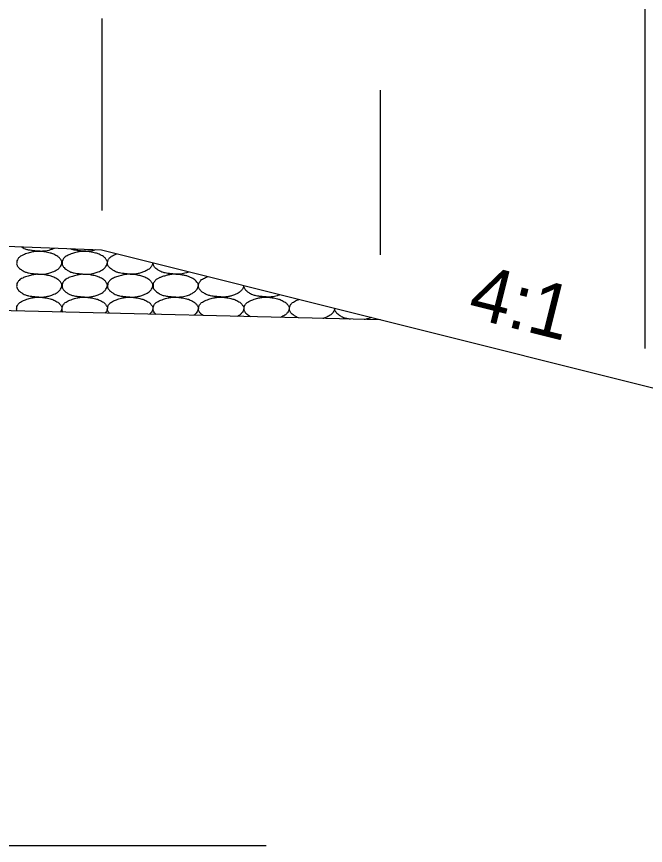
# Model space of a CAD drawing. Extents: x 1671357 to 13005564, y 567358 to 14261451.
# Drawn here: x 12758470.84 to 12758477.78, y 14259921.37 to 14259930.53 of the extents above; entities that cross this region are included whole.
import ezdxf

# ---------------------------------------------------------------- set-up
doc = ezdxf.new("R2010")
doc.units = 0
doc.layers.add('Default', color=7, linetype='Continuous')
doc.layers.add('R_Draft', color=7, linetype='Continuous')

msp = doc.modelspace()

# ---------------------------------------------------------------- linework, layer by layer
at = {"layer": 'Default'}
for p, q in [((12758477.7826, 14259926.8614), (12758477.7826, 14259931.0353)), ((12758471.7821, 14259928.3843), (12758471.7821, 14259930.5053)), ((12758474.8551, 14259927.8956), (12758474.8551, 14259929.7166)), ((12758471.7754, 14259927.947), (12758467.7783, 14259928.1069)), ((12758480.854, 14259925.6767), (12758471.7754, 14259927.947)), ((12758474.8551, 14259927.1769), (12758456.7618, 14259927.6286))]:
    msp.add_line(p, q, dxfattribs=at)
at = {"layer": 'R_Draft'}
msp.add_line((12758441.146, 14259921.3734), (12758473.5951, 14259921.3734), dxfattribs=at)
for points in [[(12758471.2523, 14259927.9679), (12758471.2407, 14259927.9624), (12758471.2289, 14259927.9576), (12758471.188, 14259927.9447), (12758471.1597, 14259927.9375), (12758471.1158, 14259927.9348), (12758471.101, 14259927.9347), (12758471.0644, 14259927.9371), (12758471.0424, 14259927.9393), (12758470.9962, 14259927.9443), (12758470.9723, 14259927.9481), (12758470.9288, 14259927.9582), (12758470.9119, 14259927.9687), (12758470.8929, 14259927.9806), (12758470.8915, 14259927.9815), (12758470.8901, 14259927.9824)], [(12758471.0864, 14259927.9331), (12758471.1157, 14259927.9335), (12758471.1451, 14259927.9291), (12758471.2102, 14259927.9158), (12758471.2432, 14259927.9049), (12758471.2986, 14259927.8752), (12758471.3137, 14259927.8591), (12758471.3347, 14259927.8276), (12758471.3381, 14259927.8167), (12758471.333, 14259927.7883), (12758471.3233, 14259927.7696), (12758471.299, 14259927.7426), (12758471.2898, 14259927.7355), (12758471.2583, 14259927.7176), (12758471.2384, 14259927.708), (12758471.188, 14259927.6921), (12758471.1597, 14259927.6849), (12758471.1158, 14259927.6822), (12758471.101, 14259927.6821), (12758471.0644, 14259927.6845), (12758471.0424, 14259927.6867), (12758470.9962, 14259927.6917), (12758470.9723, 14259927.6955), (12758470.9288, 14259927.7056), (12758470.9119, 14259927.7161), (12758470.8745, 14259927.7395), (12758470.8584, 14259927.7516), (12758470.8372, 14259927.7841), (12758470.8357, 14259927.7959), (12758470.8373, 14259927.8233), (12758470.8407, 14259927.8396), (12758470.8642, 14259927.8707), (12758470.877, 14259927.8791), (12758470.9055, 14259927.8939), (12758470.9185, 14259927.9004), (12758470.9523, 14259927.9118), (12758470.9721, 14259927.9178), (12758471.005, 14259927.9264), (12758471.0176, 14259927.9291), (12758471.0489, 14259927.934), (12758471.0678, 14259927.9347), (12758471.0864, 14259927.9331)], [(12758471.5888, 14259927.9331), (12758471.6181, 14259927.9335), (12758471.6475, 14259927.9291), (12758471.7126, 14259927.9158), (12758471.7456, 14259927.9049), (12758471.801, 14259927.8752), (12758471.8161, 14259927.8591), (12758471.8372, 14259927.8276), (12758471.8406, 14259927.8167), (12758471.8355, 14259927.7883), (12758471.8257, 14259927.7696), (12758471.8015, 14259927.7426), (12758471.7922, 14259927.7355), (12758471.7607, 14259927.7176), (12758471.7408, 14259927.708), (12758471.6904, 14259927.6921), (12758471.6621, 14259927.6849), (12758471.6182, 14259927.6822), (12758471.6034, 14259927.6821), (12758471.5668, 14259927.6845), (12758471.5448, 14259927.6867), (12758471.4986, 14259927.6917), (12758471.4747, 14259927.6955), (12758471.4312, 14259927.7056), (12758471.4143, 14259927.7161), (12758471.3769, 14259927.7395), (12758471.3608, 14259927.7516), (12758471.3396, 14259927.7841), (12758471.3381, 14259927.7959), (12758471.3397, 14259927.8233), (12758471.3431, 14259927.8396), (12758471.3666, 14259927.8707), (12758471.3794, 14259927.8791), (12758471.408, 14259927.8939), (12758471.4209, 14259927.9004), (12758471.4547, 14259927.9118), (12758471.4745, 14259927.9178), (12758471.5074, 14259927.9264), (12758471.52, 14259927.9291), (12758471.5513, 14259927.934), (12758471.5703, 14259927.9347), (12758471.5888, 14259927.9331)], [(12758471.7061, 14259927.9498), (12758471.682, 14259927.9427), (12758471.6577, 14259927.9372), (12758471.6182, 14259927.9348), (12758471.6034, 14259927.9347), (12758471.5668, 14259927.9371), (12758471.5448, 14259927.9393), (12758471.4986, 14259927.9443), (12758471.4747, 14259927.9481), (12758471.4436, 14259927.9553), (12758471.4367, 14259927.9578), (12758471.4301, 14259927.9608)], [(12758472.341, 14259927.8056), (12758472.3374, 14259927.7873), (12758472.3277, 14259927.7692), (12758472.3039, 14259927.7426), (12758472.2946, 14259927.7355), (12758472.2631, 14259927.7176), (12758472.2432, 14259927.708), (12758472.1929, 14259927.6921), (12758472.1645, 14259927.6849), (12758472.1206, 14259927.6822), (12758472.1059, 14259927.6821), (12758472.0692, 14259927.6845), (12758472.0472, 14259927.6867), (12758472.001, 14259927.6917), (12758471.9771, 14259927.6955), (12758471.9336, 14259927.7056), (12758471.9167, 14259927.7161), (12758471.8793, 14259927.7395), (12758471.8632, 14259927.7516), (12758471.842, 14259927.7841), (12758471.8406, 14259927.7959), (12758471.8421, 14259927.8233), (12758471.8456, 14259927.8396), (12758471.869, 14259927.8707), (12758471.8818, 14259927.8791), (12758471.9104, 14259927.8939), (12758471.9233, 14259927.9004), (12758471.9381, 14259927.9054), (12758471.9389, 14259927.9056), (12758471.9397, 14259927.9059)], [(12758472.7384, 14259927.7062), (12758472.7336, 14259927.7044), (12758472.7287, 14259927.7026), (12758472.6953, 14259927.6921), (12758472.6669, 14259927.6849), (12758472.623, 14259927.6822), (12758472.6083, 14259927.6821), (12758472.5716, 14259927.6845), (12758472.5496, 14259927.6867), (12758472.5034, 14259927.6917), (12758472.4795, 14259927.6955), (12758472.436, 14259927.7056), (12758472.4192, 14259927.7161), (12758472.3818, 14259927.7395), (12758472.3656, 14259927.7516), (12758472.3449, 14259927.7834), (12758472.3432, 14259927.7944), (12758472.3435, 14259927.8049)], [(12758471.0864, 14259927.6805), (12758471.1157, 14259927.6809), (12758471.1451, 14259927.6765), (12758471.2102, 14259927.6632), (12758471.2432, 14259927.6523), (12758471.2986, 14259927.6226), (12758471.3137, 14259927.6065), (12758471.3347, 14259927.575), (12758471.3381, 14259927.5641), (12758471.333, 14259927.5357), (12758471.3233, 14259927.517), (12758471.299, 14259927.49), (12758471.2898, 14259927.4829), (12758471.2583, 14259927.465), (12758471.2384, 14259927.4554), (12758471.188, 14259927.4395), (12758471.1597, 14259927.4323), (12758471.1158, 14259927.4295), (12758471.101, 14259927.4295), (12758471.0644, 14259927.4319), (12758471.0424, 14259927.4341), (12758470.9962, 14259927.4391), (12758470.9723, 14259927.4429), (12758470.9288, 14259927.453), (12758470.9119, 14259927.4635), (12758470.8745, 14259927.4869), (12758470.8584, 14259927.499), (12758470.8372, 14259927.5315), (12758470.8357, 14259927.5433), (12758470.8373, 14259927.5707), (12758470.8407, 14259927.587), (12758470.8642, 14259927.6181), (12758470.877, 14259927.6265), (12758470.9055, 14259927.6413), (12758470.9185, 14259927.6478), (12758470.9523, 14259927.6592), (12758470.9721, 14259927.6652), (12758471.005, 14259927.6738), (12758471.0176, 14259927.6765), (12758471.0489, 14259927.6814), (12758471.0678, 14259927.6821), (12758471.0864, 14259927.6805)], [(12758471.5888, 14259927.6805), (12758471.6181, 14259927.6809), (12758471.6475, 14259927.6765), (12758471.7126, 14259927.6632), (12758471.7456, 14259927.6523), (12758471.801, 14259927.6226), (12758471.8161, 14259927.6065), (12758471.8372, 14259927.575), (12758471.8406, 14259927.5641), (12758471.8355, 14259927.5357), (12758471.8257, 14259927.517), (12758471.8015, 14259927.49), (12758471.7922, 14259927.4829), (12758471.7607, 14259927.465), (12758471.7408, 14259927.4554), (12758471.6904, 14259927.4395), (12758471.6621, 14259927.4323), (12758471.6182, 14259927.4295), (12758471.6034, 14259927.4295), (12758471.5668, 14259927.4319), (12758471.5448, 14259927.4341), (12758471.4986, 14259927.4391), (12758471.4747, 14259927.4429), (12758471.4312, 14259927.453), (12758471.4143, 14259927.4635), (12758471.3769, 14259927.4869), (12758471.3608, 14259927.499), (12758471.3396, 14259927.5315), (12758471.3381, 14259927.5433), (12758471.3397, 14259927.5707), (12758471.3431, 14259927.587), (12758471.3666, 14259927.6181), (12758471.3794, 14259927.6265), (12758471.408, 14259927.6413), (12758471.4209, 14259927.6478), (12758471.4547, 14259927.6592), (12758471.4745, 14259927.6652), (12758471.5074, 14259927.6738), (12758471.52, 14259927.6765), (12758471.5513, 14259927.6814), (12758471.5703, 14259927.6821), (12758471.5888, 14259927.6805)], [(12758472.0912, 14259927.6805), (12758472.1205, 14259927.6809), (12758472.1499, 14259927.6765), (12758472.215, 14259927.6632), (12758472.248, 14259927.6523), (12758472.3034, 14259927.6226), (12758472.3186, 14259927.6065), (12758472.3396, 14259927.575), (12758472.343, 14259927.5641), (12758472.3379, 14259927.5357), (12758472.3281, 14259927.517), (12758472.3039, 14259927.49), (12758472.2946, 14259927.4829), (12758472.2631, 14259927.465), (12758472.2432, 14259927.4554), (12758472.1929, 14259927.4395), (12758472.1645, 14259927.4323), (12758472.1206, 14259927.4295), (12758472.1059, 14259927.4295), (12758472.0692, 14259927.4319), (12758472.0472, 14259927.4341), (12758472.001, 14259927.4391), (12758471.9771, 14259927.4429), (12758471.9336, 14259927.453), (12758471.9167, 14259927.4635), (12758471.8793, 14259927.4869), (12758471.8632, 14259927.499), (12758471.842, 14259927.5315), (12758471.8406, 14259927.5433), (12758471.8421, 14259927.5707), (12758471.8456, 14259927.587), (12758471.869, 14259927.6181), (12758471.8818, 14259927.6265), (12758471.9104, 14259927.6413), (12758471.9233, 14259927.6478), (12758471.9571, 14259927.6592), (12758471.9769, 14259927.6652), (12758472.0098, 14259927.6738), (12758472.0224, 14259927.6765), (12758472.0538, 14259927.6814), (12758472.0727, 14259927.6821), (12758472.0912, 14259927.6805)], [(12758472.5937, 14259927.6805), (12758472.6229, 14259927.6809), (12758472.6523, 14259927.6765), (12758472.6817, 14259927.6705), (12758472.7175, 14259927.6632), (12758472.7505, 14259927.6523), (12758472.7837, 14259927.6345), (12758472.8058, 14259927.6226), (12758472.821, 14259927.6065), (12758472.8357, 14259927.5845), (12758472.842, 14259927.575), (12758472.8454, 14259927.5641), (12758472.8437, 14259927.5545), (12758472.8403, 14259927.5357), (12758472.8305, 14259927.517), (12758472.8157, 14259927.5005), (12758472.8063, 14259927.49), (12758472.7971, 14259927.4829), (12758472.7857, 14259927.4765), (12758472.7655, 14259927.465), (12758472.7456, 14259927.4554), (12758472.7237, 14259927.4485), (12758472.6953, 14259927.4395), (12758472.6669, 14259927.4323), (12758472.6377, 14259927.4305), (12758472.623, 14259927.4295), (12758472.6083, 14259927.4295), (12758472.5937, 14259927.4305), (12758472.5716, 14259927.4319), (12758472.5496, 14259927.4341), (12758472.5276, 14259927.4365), (12758472.5034, 14259927.4391), (12758472.4795, 14259927.4429), (12758472.4556, 14259927.4485), (12758472.436, 14259927.453), (12758472.4192, 14259927.4635), (12758472.4016, 14259927.4745), (12758472.3818, 14259927.4869), (12758472.3656, 14259927.499), (12758472.3516, 14259927.5205), (12758472.3444, 14259927.5315), (12758472.343, 14259927.5433), (12758472.3436, 14259927.5545), (12758472.3446, 14259927.5707), (12758472.348, 14259927.587), (12758472.3596, 14259927.6025), (12758472.3714, 14259927.6181), (12758472.3843, 14259927.6265), (12758472.3996, 14259927.6345), (12758472.4128, 14259927.6413), (12758472.4257, 14259927.6478), (12758472.4396, 14259927.6525), (12758472.4595, 14259927.6592), (12758472.4793, 14259927.6652), (12758472.4996, 14259927.6705), (12758472.5122, 14259927.6738), (12758472.5248, 14259927.6765), (12758472.5376, 14259927.6785), (12758472.5562, 14259927.6814), (12758472.5751, 14259927.6821), (12758472.5937, 14259927.6805)], [(12758473.3461, 14259927.5542), (12758473.3426, 14259927.5355), (12758473.3329, 14259927.517), (12758473.3087, 14259927.49), (12758473.2995, 14259927.4829), (12758473.2679, 14259927.465), (12758473.2481, 14259927.4554), (12758473.1977, 14259927.4395), (12758473.1693, 14259927.4323), (12758473.1254, 14259927.4295), (12758473.1107, 14259927.4295), (12758473.074, 14259927.4319), (12758473.0521, 14259927.4341), (12758473.0058, 14259927.4391), (12758472.9819, 14259927.4429), (12758472.9384, 14259927.453), (12758472.9216, 14259927.4635), (12758472.8842, 14259927.4869), (12758472.868, 14259927.499), (12758472.8468, 14259927.5315), (12758472.8454, 14259927.5433), (12758472.847, 14259927.5707), (12758472.8504, 14259927.587), (12758472.8738, 14259927.6181), (12758472.8867, 14259927.6265), (12758472.9152, 14259927.6413), (12758472.9281, 14259927.6478), (12758472.9436, 14259927.653), (12758472.9452, 14259927.6536), (12758472.9468, 14259927.6541)], [(12758473.7453, 14259927.4544), (12758473.7398, 14259927.4523), (12758473.7342, 14259927.4503), (12758473.7001, 14259927.4395), (12758473.6717, 14259927.4323), (12758473.6278, 14259927.4295), (12758473.6131, 14259927.4295), (12758473.5765, 14259927.4319), (12758473.5545, 14259927.4341), (12758473.5083, 14259927.4391), (12758473.4844, 14259927.4429), (12758473.4409, 14259927.453), (12758473.424, 14259927.4635), (12758473.3866, 14259927.4869), (12758473.3705, 14259927.499), (12758473.3494, 14259927.5312), (12758473.3479, 14259927.5427), (12758473.3484, 14259927.5537)], [(12758470.8397, 14259927.2771), (12758470.8365, 14259927.2853), (12758470.8359, 14259927.2938), (12758470.8373, 14259927.3181), (12758470.8407, 14259927.3344), (12758470.8642, 14259927.3655), (12758470.877, 14259927.3739), (12758470.9055, 14259927.3887), (12758470.9185, 14259927.3952), (12758470.9523, 14259927.4066), (12758470.9721, 14259927.4126), (12758471.005, 14259927.4212), (12758471.0176, 14259927.4239), (12758471.0489, 14259927.4288), (12758471.0678, 14259927.4295), (12758471.0864, 14259927.4279)], [(12758471.3491, 14259927.2644), (12758471.3483, 14259927.2655), (12758471.3476, 14259927.2667), (12758471.3396, 14259927.2789), (12758471.3381, 14259927.2907), (12758471.3397, 14259927.3181), (12758471.3431, 14259927.3344), (12758471.3666, 14259927.3655), (12758471.3794, 14259927.3739), (12758471.408, 14259927.3887), (12758471.4209, 14259927.3952), (12758471.4547, 14259927.4066), (12758471.4745, 14259927.4126), (12758471.5074, 14259927.4212), (12758471.52, 14259927.4239), (12758471.5513, 14259927.4288), (12758471.5703, 14259927.4295), (12758471.5888, 14259927.4279)], [(12758471.8617, 14259927.2516), (12758471.8574, 14259927.2564), (12758471.8532, 14259927.2618), (12758471.842, 14259927.2789), (12758471.8406, 14259927.2907), (12758471.8421, 14259927.3181), (12758471.8456, 14259927.3344), (12758471.869, 14259927.3655), (12758471.8818, 14259927.3739), (12758471.9104, 14259927.3887), (12758471.9233, 14259927.3952), (12758471.9571, 14259927.4066), (12758471.9769, 14259927.4126), (12758472.0098, 14259927.4212), (12758472.0224, 14259927.4239), (12758472.0538, 14259927.4288), (12758472.0727, 14259927.4295), (12758472.0912, 14259927.4279)], [(12758472.3777, 14259927.2387), (12758472.3681, 14259927.2466), (12758472.3595, 14259927.2558), (12758472.3444, 14259927.2789), (12758472.343, 14259927.2907), (12758472.3446, 14259927.3181), (12758472.348, 14259927.3344), (12758472.3714, 14259927.3655), (12758472.3843, 14259927.3739), (12758472.4128, 14259927.3887), (12758472.4257, 14259927.3952), (12758472.4595, 14259927.4066), (12758472.4793, 14259927.4126), (12758472.5122, 14259927.4212), (12758472.5248, 14259927.4239), (12758472.5562, 14259927.4288), (12758472.5751, 14259927.4295), (12758472.5937, 14259927.4279)], [(12758472.898, 14259927.2257), (12758472.8809, 14259927.2369), (12758472.8666, 14259927.2487), (12758472.8468, 14259927.2789), (12758472.8454, 14259927.2907), (12758472.847, 14259927.3181), (12758472.8504, 14259927.3344), (12758472.8738, 14259927.3655), (12758472.8867, 14259927.3739), (12758472.9152, 14259927.3887), (12758472.9281, 14259927.3952), (12758472.9619, 14259927.4066), (12758472.9818, 14259927.4126), (12758473.0146, 14259927.4212), (12758473.0272, 14259927.4239), (12758473.0586, 14259927.4288), (12758473.0775, 14259927.4295), (12758473.0961, 14259927.4279)], [(12758473.4215, 14259927.2127), (12758473.4165, 14259927.2156), (12758473.4115, 14259927.2187), (12758473.3866, 14259927.2343), (12758473.3705, 14259927.2464), (12758473.3493, 14259927.2789), (12758473.3478, 14259927.2907), (12758473.3494, 14259927.3181), (12758473.3528, 14259927.3344), (12758473.3763, 14259927.3655), (12758473.3891, 14259927.3739), (12758473.4176, 14259927.3887), (12758473.4306, 14259927.3952), (12758473.4643, 14259927.4066), (12758473.4842, 14259927.4126), (12758473.5171, 14259927.4212), (12758473.5296, 14259927.4239), (12758473.561, 14259927.4288), (12758473.5799, 14259927.4295), (12758473.5985, 14259927.4279)], [(12758471.0864, 14259927.4279), (12758471.1157, 14259927.4283), (12758471.1451, 14259927.4239), (12758471.2102, 14259927.4106), (12758471.2432, 14259927.3997), (12758471.2986, 14259927.37), (12758471.3137, 14259927.3539), (12758471.3347, 14259927.3224), (12758471.3381, 14259927.3115), (12758471.3342, 14259927.2894), (12758471.3291, 14259927.2769), (12758471.3215, 14259927.2651)], [(12758471.5888, 14259927.4279), (12758471.6181, 14259927.4283), (12758471.6475, 14259927.4239), (12758471.7126, 14259927.4106), (12758471.7456, 14259927.3997), (12758471.801, 14259927.37), (12758471.8161, 14259927.3539), (12758471.8372, 14259927.3224), (12758471.8406, 14259927.3115), (12758471.8358, 14259927.2849), (12758471.8275, 14259927.2681), (12758471.815, 14259927.2528)], [(12758472.0912, 14259927.4279), (12758472.1205, 14259927.4283), (12758472.1499, 14259927.4239), (12758472.215, 14259927.4106), (12758472.248, 14259927.3997), (12758472.3034, 14259927.37), (12758472.3186, 14259927.3539), (12758472.3396, 14259927.3224), (12758472.343, 14259927.3115), (12758472.3379, 14259927.2831), (12758472.3281, 14259927.2644), (12758472.3109, 14259927.2452), (12758472.3085, 14259927.2428), (12758472.3061, 14259927.2405)], [(12758472.5937, 14259927.4279), (12758472.6229, 14259927.4283), (12758472.6523, 14259927.4239), (12758472.7175, 14259927.4106), (12758472.7505, 14259927.3997), (12758472.8058, 14259927.37), (12758472.821, 14259927.3539), (12758472.842, 14259927.3224), (12758472.8454, 14259927.3115), (12758472.8403, 14259927.2831), (12758472.8305, 14259927.2644), (12758472.8084, 14259927.2398), (12758472.8012, 14259927.2337), (12758472.7931, 14259927.2284)], [(12758473.0961, 14259927.4279), (12758473.1254, 14259927.4283), (12758473.1548, 14259927.4239), (12758473.2199, 14259927.4106), (12758473.2529, 14259927.3997), (12758473.3082, 14259927.37), (12758473.3234, 14259927.3539), (12758473.3444, 14259927.3224), (12758473.3478, 14259927.3115), (12758473.3427, 14259927.2831), (12758473.3329, 14259927.2644), (12758473.3087, 14259927.2374), (12758473.2995, 14259927.2303), (12758473.2835, 14259927.2213), (12758473.2789, 14259927.2188), (12758473.2744, 14259927.2163)], [(12758473.5985, 14259927.4279), (12758473.6278, 14259927.4283), (12758473.6572, 14259927.4239), (12758473.7223, 14259927.4106), (12758473.7553, 14259927.3997), (12758473.8107, 14259927.37), (12758473.8258, 14259927.3539), (12758473.8468, 14259927.3224), (12758473.8502, 14259927.3115), (12758473.8451, 14259927.2831), (12758473.8353, 14259927.2644), (12758473.8111, 14259927.2374), (12758473.8019, 14259927.2303), (12758473.7777, 14259927.2166), (12758473.7649, 14259927.21), (12758473.7517, 14259927.2044)], [(12758473.9509, 14259927.1995), (12758473.9362, 14259927.2048), (12758473.9227, 14259927.2132), (12758473.889, 14259927.2343), (12758473.8729, 14259927.2464), (12758473.8517, 14259927.2789), (12758473.8502, 14259927.2907), (12758473.8518, 14259927.3181), (12758473.8552, 14259927.3344), (12758473.8787, 14259927.3655), (12758473.8915, 14259927.3739), (12758473.92, 14259927.3887), (12758473.933, 14259927.3952), (12758473.9492, 14259927.4007), (12758473.9516, 14259927.4015), (12758473.9539, 14259927.4022)], [(12758474.3511, 14259927.3029), (12758474.351, 14259927.3026), (12758474.351, 14259927.3022), (12758474.3475, 14259927.2831), (12758474.3378, 14259927.2644), (12758474.3136, 14259927.2374), (12758474.3043, 14259927.2303), (12758474.2728, 14259927.2124), (12758474.2529, 14259927.2028), (12758474.2275, 14259927.1948), (12758474.2241, 14259927.1937), (12758474.2207, 14259927.1927)], [(12758474.5269, 14259927.1851), (12758474.5063, 14259927.1876), (12758474.4858, 14259927.1911), (12758474.4457, 14259927.2004), (12758474.4288, 14259927.2109), (12758474.3914, 14259927.2343), (12758474.3753, 14259927.2464), (12758474.3541, 14259927.2789), (12758474.3527, 14259927.2907), (12758474.3533, 14259927.302), (12758474.3533, 14259927.3022), (12758474.3533, 14259927.3024)], [(12758474.7522, 14259927.2026), (12758474.746, 14259927.2002), (12758474.7398, 14259927.1979), (12758474.7144, 14259927.1899), (12758474.6955, 14259927.1847), (12758474.6763, 14259927.1813)]]:
    msp.add_open_spline(points, degree=3, dxfattribs=at)

# ---------------------------------------------------------------- texts
msp.add_text('4:1', height=0.60006, rotation=345.96, dxfattribs=at).set_placement((12758475.8017, 14259927.2148))

doc.saveas('drawing.dxf')
